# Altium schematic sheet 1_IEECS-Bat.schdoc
size 708 x 330 mm; Name: A_A3; Symbol: A_A3; Device: A_A3; @Project Name: IEECS-Design-Bat; REV: 1.0; Date: 2022-09-18; Sheet: 1/1; Draw By: Aimmecat; Company: Your Company; Convert to PCB: yes; Add into BOM: yes
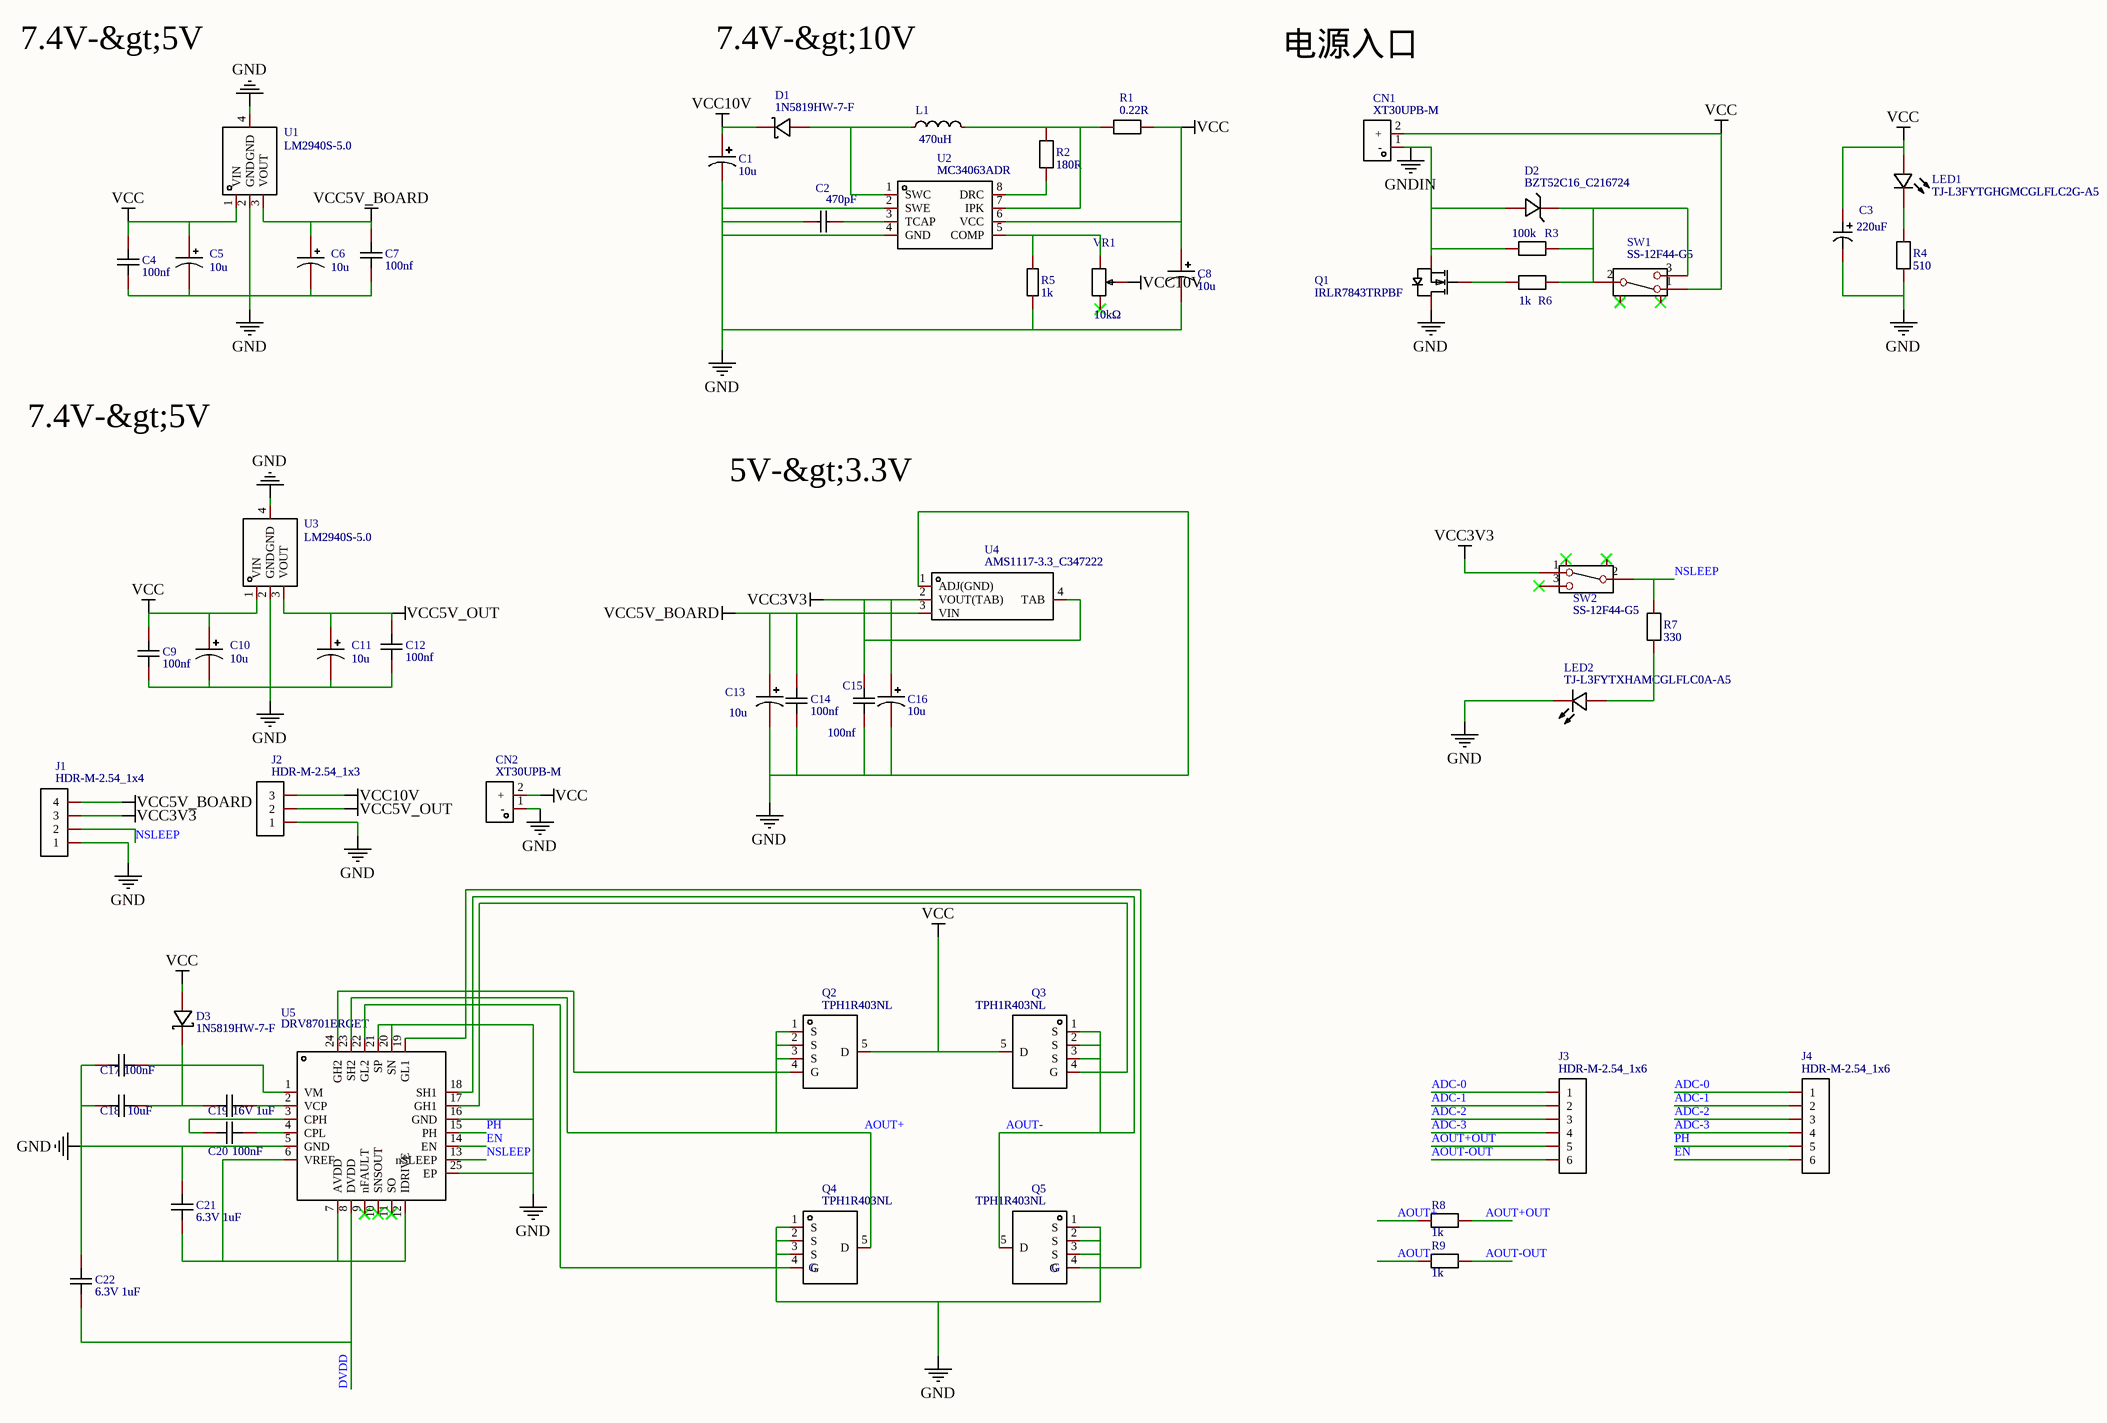
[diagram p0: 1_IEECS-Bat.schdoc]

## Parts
C1  10u  [CASE-A_3216]
C2  470pF  [C0805]
C3  220uF  [CAP-SMD_BD6.3-L6.6-W6.6-FD]
C4  100nf  [C0603]
C5  10u  [CASE-A_3216]
C6  10u  [CASE-A_3216]
C7  100nf  [C0603]
C8  10u  [CASE-A_3216]
C9  100nf  [C0603]
C10  10u  [CASE-A_3216]
C11  10u  [CASE-A_3216]
C12  100nf  [C0603]
C13  10u  [CASE-A_3216]
C14  100nf  [C0603]
C15  100nf  [C0603]
C16  10u  [CASE-A_3216]
C17  100nF  [C0603]
C18  10uF  [C0603]
C19  16V 1uF  [C0603]
C20  100nF  [C0603]
C21  6.3V 1uF  [C0603]
C22  6.3V 1uF  [C0603]
CN1  XT30UPB-M  [CONN-TH_XT30UPB-M]
CN2  XT30UPB-M  [CONN-TH_XT30UPB-M]
D1  1N5819HW-7-F  [SOD-123_L2.8-W1.8-LS3.7-FD]
D2  BZT52C16_C216724  [SOD-123_L2.8-W1.8-LS3.7-RD]
D3  1N5819HW-7-F  [SOD-123_L2.8-W1.8-LS3.7-FD]
J1  HDR-M-2.54_1x4  [HDR-M-2.54_1X4]
J2  HDR-M-2.54_1x3  [HDR-M-2.54_1X3]
J3  HDR-M-2.54_1x6  [HDR-M-2.54_1X6]
J4  HDR-M-2.54_1x6  [HDR-M-2.54_1X6]
L1  470uH  [IND-SMD_L6.0-W6.0_SWPA6045S]
LED1  TJ-L3FYTGHGMCGLFLC2G-A5  [LED-TH_BD3.9-P2.54-FD]
LED2  TJ-L3FYTXHAMCGLFLC0A-A5  [LED-TH_BD3.0-P2.54-FD]
Q1  IRLR7843TRPBF  [TO-252-2_L6.5-W6.1-P4.58-LS10.0-TR]
Q2  TPH1R403NL  [POWERVDFN-8_L6.2-W5.2-P1.27-LS6.0-BL]
Q3  TPH1R403NL  [POWERVDFN-8_L6.2-W5.2-P1.27-LS6.0-BL]
Q4  TPH1R403NL  NAME: G  [POWERVDFN-8_L6.2-W5.2-P1.27-LS6.0-BL]
Q5  TPH1R403NL  NAME: G  [POWERVDFN-8_L6.2-W5.2-P1.27-LS6.0-BL]
R1  0.22R  [R0603]
R2  180R  [R0603]
R3  100k  [R0603]
R4  510  [R0603]
R5  1k  [R0805]
R6  1k  [R0603]
R7  330  [R0603]
R8  1k  [R0603]
R9  1k  [R0603]
SW1  SS-12F44-G5  [SW-TH_SS-12F44-G5]
SW2  SS-12F44-G5  [SW-TH_SS-12F44-G5]
U1  LM2940S-5.0  [SOT-223-3_L6.5-W3.4-P2.30-LS7.0-BR]
U2  MC34063ADR  [SOIC-8_L4.9-W3.9-P1.27-LS6.0-BL]
U3  LM2940S-5.0  [SOT-223-3_L6.5-W3.4-P2.30-LS7.0-BR]
U4  AMS1117-3.3_C347222  [SOT-223_L6.7-W3.5-P2.30-BR]
U5  DRV8701ERGET  [VQFN-24_L4.0-W4.0-P0.50-LS4.0-BL-EP]
VR1  10kΩ  [RES-ADJ-TH_3362P]

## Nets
GND: C1.2 C2.1 C3.2 C4.1 C5.2 C6.2 C7.1 C8.2 C9.1 C10.2 C11.2 C12.1 C13.2 C14.1 C15.1 C16.2 C17.1 C18.1 C21.2 C22.2 CN2.1(-) J1.1 J2.1 LED2.2(C) Q1.4(D) Q4.1(S) Q4.2(S) Q4.3(S) Q5.1(S) Q5.2(S) Q5.3(S) R4.1 R5.1 U1.2(GND) U1.4(GND) U2.2(SWE) U2.4(GND) U3.2(GND) U3.4(GND) U4.1(ADJ(GND)) U5.5(GND) U5.16(GND) U5.20(SN) U5.21(SP) U5.25(EP)
GNDIN: CN1.1(-) D2.2(A) Q1.3(S) R3.1
VCC: C3.1 C4.2 C5.1 C8.1 C9.2 C10.1 CN1.2(+) CN2.2(+) D3.1(A) LED1.1(+) Q2.5(D) Q3.5(D) R1.2 SW1.1 U1.1(VIN) U2.6(VCC) U3.1(VIN)
VCC3V3: C15.2 C16.1 J1.3 SW2.1 U4.2(VOUT(TAB)) U4.4(TAB)
VCC5V_BOARD: C6.1 C7.2 C13.1 C14.2 J1.4 U1.3(VOUT) U4.3(VIN)
VCC5V_OUT: C11.1 C12.2 J2.2 U3.3(VOUT)
VCC10V: C1.1 D1.2(K) J2.3 VR1.2
ADC-0: J3.1 J4.1
ADC-1: J3.2 J4.2
ADC-2: J3.3 J4.3
ADC-3: J3.4 J4.4
AOUT+: Q2.1(S) Q2.2(S) Q2.3(S) Q4.5(D) R8.2 U5.23(SH2)
AOUT+OUT: J3.5 R8.1
AOUT-: Q3.1(S) Q3.2(S) Q3.3(S) Q5.5(D) R9.2 U5.18(SH1)
AOUT-OUT: J3.6 R9.1
DVDD: C22.1 U5.8(DVDD)
EN: J4.6 U5.14(EN)
NSLEEP: J1.2 R7.2 SW2.2 U5.13(nSLEEP)
PH: J4.5 U5.15(PH)
NetC2_2: C2.2 U2.3(TCAP)
NetC17_2: C17.2 C18.2 C19.1 D3.2(K) U5.1(VM)
NetC19_2: C19.2 U5.2(VCP)
NetC20_1: C20.1 U5.3(CPH)
NetC20_2: C20.2 U5.4(CPL)
NetC21_1: C21.1 U5.6(VREF) U5.7(AVDD) U5.12(IDRIVE)
NetD1_1: D1.1(A) L1.1 U2.1(SWC)
NetD2_1: D2.1(K) R3.2 R6.2 SW1.2 SW1.3
NetL1_2: L1.2 R1.1 R2.2 U2.7(IPK)
NetLED1_2: LED1.2(-) R4.2
NetLED2_1: LED2.1(A) R7.1
NetQ1_1: Q1.1(G) R6.1
NetQ2_4: Q2.4(G) U5.24(GH2)
NetQ3_4: Q3.4(G) U5.17(GH1)
NetQ4_4: Q4.4(G) U5.22(GL2)
NetQ5_4: Q5.4(G) U5.19(GL1)
NetR2_1: R2.1 U2.8(DRC)
NetR5_2: R5.2 U2.5(COMP) VR1.3

Not connected (* = marked no-connect by the designer): SW1 4* 5*; SW2 3* 4* 5*; U5 9(nFAULT)* 10(SNSOUT)* 11(SO)*; VR1 1*

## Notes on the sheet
- 7.4V-&gt;5V
- 7.4V-&gt;10V
- 电源入口
- 5V-&gt;3.3V

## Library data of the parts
C1 C5 C6 C8 C10 C11 C13 C16 = 10u: Convert to PCB: yes
C2 = CC0805KRX7R9BB471: Manufacturer: YAGEO; Convert to PCB: yes
C3 = RVT220UF16V67RV0015: 容值:220uF;额定电压:16V;工作寿命:2000hrs@105;; Manufacturer: KNSCHA(科尼盛); Add into BOM: yes; Rated Voltage: 16V
C4 C7 C9 C12 C14 C15 = 100nf: Convert to PCB: yes
C17 C20 = 100nF: Convert to PCB: yes; NAME: 2
C18 = 10uF: Convert to PCB: yes; NAME: 2
C19 = 16V 1uF: Convert to PCB: yes; NAME: 2
C21 C22 = 6.3V 1uF: Convert to PCB: yes; NAME: 2
CN1 CN2 = XT30UPB-M: Manufacturer: Changzhou Amass Elec; Convert to PCB: yes
D1 = 1N5819HW-7-F: Manufacturer: DIODES; Paste Type: expand; Convert to PCB: yes
D2 = BZT52C16: Manufacturer: SK; Convert to PCB: yes
D3 = 1N5819HW-7-F: Manufacturer: DIODES; Convert to PCB: yes; NAME: K; NUMBER: 2
J1 = HDR-M-2.54_1x4: Convert to PCB: yes
J2 = HDR-M-2.54_1x3: Convert to PCB: yes
J3 J4 = HDR-M-2.54_1x6: Convert to PCB: yes
L1 = SWPA6045S471MT: 电感值:470uH;精度:±20%;额定电流:420mA;直流电阻(DCR):1.8Ω;; Manufacturer: Sunlord(顺络); Add into BOM: yes; Tolerance: ±20%; Rated Current: 420mA; DC Resistance (DCR): 1.8Ω
LED1 = TJ-L3FYTGHGMCGLFLC2G-A5: Manufacturer: TOGIALED; Convert to PCB: yes
LED2 = TJ-L3FYTXHAMCGLFLC0A-A5: Manufacturer: TOGIALED; Convert to PCB: yes
Q1 = IRLR7843TRPBF: Manufacturer: IR; Convert to PCB: yes
Q2-Q5 = TPH1R403NL: Manufacturer: TOSHIBA; Convert to PCB: yes
R1 = 0.22R: Convert to PCB: yes
R2 = 180R: Convert to PCB: yes
R3 = 100k: Convert to PCB: yes
R4 = 510: Convert to PCB: yes
R5 = RMC08055.1K5%N: Manufacturer: Tyohm; Symbol: 14k; Convert to PCB: yes
R6 = 1k: Convert to PCB: yes
R7 = 330: Convert to PCB: yes
R8 R9 = 510: Convert to PCB: yes; NAME: 1
SW1 SW2 = SS-12F44-G5: Manufacturer: Rectangular Connectors - Contacts; Convert to PCB: yes
U1 U3 = LM2940S-5.0: 输出类型:-;; Manufacturer: HTC; Add into BOM: yes
U2 = MC34063ADR: Manufacturer: TI; Paste Type: expand; Convert to PCB: yes
U4 = AMS1117-3.3: Manufacturer: Youtai Semiconductor Co., Ltd.; Convert to PCB: yes
U5 = DRV8701ERGET: Manufacturer: TI; Convert to PCB: yes
VR1 = 3362P-1-103LF: 阻值:10kΩ;精度:±10%;; Manufacturer: BOURNS; Add into BOM: yes; Tolerance: ±10%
